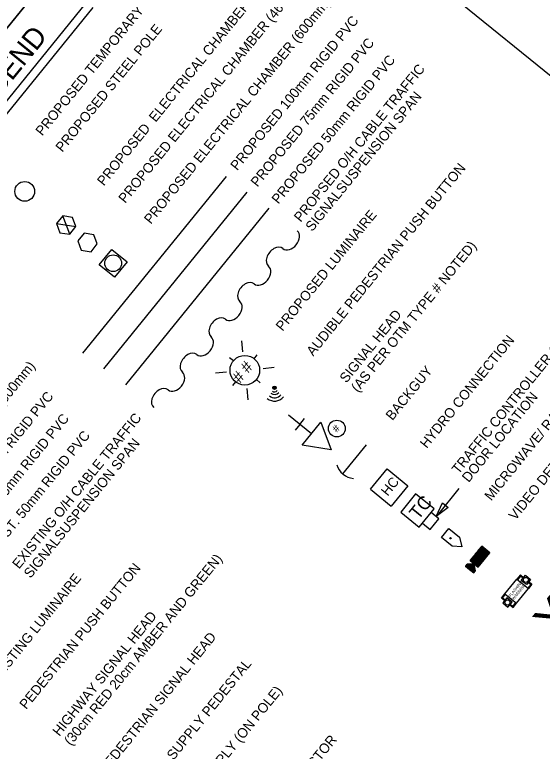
# Model space of a CAD drawing. Extents: x 592613 to 600223, y 4837996 to 4840103.
# Drawn here: x 592677.9 to 592701.09, y 4838962.54 to 4838994.9 of the extents above; entities that cross this region are included whole.
import ezdxf

# ---------------------------------------------------------------- set-up
doc = ezdxf.new("R2010")
doc.units = 0
for name, color, linetype in [('ENG_BORDER', 7, 'Continuous'), ('TCS_100mm-NEW', 7, 'Continuous'), ('TCS_50mm-NEW', 7, 'Continuous'), ('TCS_75mm-NEW', 7, 'Continuous'), ('TCS_BACKGUY', 7, 'Continuous'), ('TCS_CONTROLLER', 7, 'Continuous'), ('TCS_ELEC-CHAMBER-NEW', 7, 'Continuous'), ('TCS_HYDROSUPPLY', 7, 'Continuous'), ('TCS_LEGEND', 7, 'Continuous'), ('TCS_LUMINAIRE-NEW', 7, 'Continuous'), ('TCS_POLE-NEW', 7, 'Continuous'), ('TCS_PUSHBUTTON', 7, 'Continuous'), ('TCS_RADAR', 7, 'Continuous'), ('TCS_REMOVAL', 7, 'Continuous'), ('TCS_SIGN', 7, 'Continuous'), ('TCS_SIGNALHEAD', 7, 'Continuous'), ('TCS_SPAN-NEW', 7, 'Continuous'), ('TCS_VIDEO', 7, 'Continuous')]:
    doc.layers.add(name, color=color, linetype=linetype)

msp = doc.modelspace()

# ---------------------------------------------------------------- linework, layer by layer
at = {"layer": 'ENG_BORDER'}
msp.add_line((592790.401, 4838919.927), (592686.018, 4839004.737), dxfattribs=at)
msp.add_lwpolyline([(592783.858, 4839125.156), (592658.479, 4838970.843)], dxfattribs=at)
at = {"layer": 'TCS_100mm-NEW'}
msp.add_line((592680.903, 4838980.027), (592687.209, 4838987.788), dxfattribs=at)
at = {"layer": 'TCS_50mm-NEW'}
msp.add_line((592682.782, 4838978.641), (592689.088, 4838986.402), dxfattribs=at)
at = {"layer": 'TCS_75mm-NEW'}
msp.add_line((592681.814, 4838979.334), (592688.12, 4838987.095), dxfattribs=at)
at = {"layer": 'TCS_BACKGUY'}
msp.add_line((592692.323, 4838974.721), (592693.358, 4838975.995), dxfattribs=at)
msp.add_arc((592692.868, 4838975.372), 0.849, 196.7975, 265.0147, dxfattribs=at)
at = {"layer": 'TCS_CONTROLLER'}
for p, q in [((592697.428, 4838974.087), (592696.523, 4838972.973)), ((592695.524, 4838973.848), (592694.868, 4838973.04)), ((592696.332, 4838973.192), (592695.524, 4838973.848)), ((592694.868, 4838973.04), (592695.676, 4838972.384)), ((592695.676, 4838972.384), (592696.332, 4838973.192)), ((592696.54, 4838972.753), (592696.204, 4838973.026)), ((592696.158, 4838972.282), (592696.54, 4838972.753)), ((592695.821, 4838972.555), (592696.158, 4838972.282))]:
    msp.add_line(p, q, dxfattribs=at)
msp.add_lwpolyline([(592696.422, 4838972.849), (592696.701, 4838973.445), (592696.948, 4838973.244), (592696.948, 4838973.244)], close=True, dxfattribs=at)
at = {"layer": 'TCS_ELEC-CHAMBER-NEW'}
for p, q in [((592680.013, 4838986.06), (592679.74, 4838985.723)), ((592680.323, 4838985.249), (592680.013, 4838986.06)), ((592680.441, 4838985.991), (592680.013, 4838986.06)), ((592680.596, 4838985.586), (592680.441, 4838985.991)), ((592679.74, 4838985.723), (592680.596, 4838985.586)), ((592679.74, 4838985.723), (592679.894, 4838985.318)), ((592679.894, 4838985.318), (592680.323, 4838985.249)), ((592680.323, 4838985.249), (592680.596, 4838985.586)), ((592680.951, 4838985.297), (592680.678, 4838984.961)), ((592681.379, 4838985.229), (592680.951, 4838985.297)), ((592681.534, 4838984.824), (592681.379, 4838985.229)), ((592680.678, 4838984.961), (592680.832, 4838984.556)), ((592681.261, 4838984.487), (592681.534, 4838984.824)), ((592680.832, 4838984.556), (592681.261, 4838984.487)), ((592681.621, 4838983.915), (592682.168, 4838984.588)), ((592682.168, 4838984.588), (592682.842, 4838984.041)), ((592682.842, 4838984.041), (592682.295, 4838983.368)), ((592682.295, 4838983.368), (592681.621, 4838983.915))]:
    msp.add_line(p, q, dxfattribs=at)
msp.add_circle((592682.231, 4838983.978), 0.367, dxfattribs=at)
at = {"layer": 'TCS_HYDROSUPPLY'}
for p, q in [((592693.54, 4838974.045), (592694.269, 4838974.942)), ((592694.269, 4838974.942), (592695.175, 4838974.205)), ((592693.54, 4838974.045), (592694.447, 4838973.308)), ((592695.175, 4838974.205), (592694.447, 4838973.308))]:
    msp.add_line(p, q, dxfattribs=at)
at = {"layer": 'TCS_LEGEND'}
for p, q in [((592666.56, 4838977.581), (592681.077, 4838995.448)), ((592666.842, 4838977.353), (592681.359, 4838995.22))]:
    msp.add_line(p, q, dxfattribs=at)
msp.add_lwpolyline([(592661.217, 4838974.213), (592683.281, 4839001.368)], dxfattribs=at)
at = {"layer": 'TCS_LUMINAIRE-NEW'}
for p, q in [((592687.934, 4838980.085), (592687.884, 4838980.57)), ((592687.513, 4838979.686), (592687.344, 4838979.823)), ((592688.428, 4838979.781), (592688.565, 4838979.949)), ((592687.209, 4838979.192), (592686.724, 4838979.142)), ((592688.826, 4838979.36), (592689.312, 4838979.41)), ((592688.523, 4838978.866), (592688.691, 4838978.729)), ((592687.607, 4838978.771), (592687.471, 4838978.603)), ((592688.101, 4838978.468), (592688.152, 4838977.982))]:
    msp.add_line(p, q, dxfattribs=at)
msp.add_circle((592688.018, 4838979.276), 0.651, dxfattribs=at)
at = {"layer": 'TCS_POLE-NEW'}
msp.add_circle((592678.343, 4838987.137), 0.434, dxfattribs=at)
at = {"layer": 'TCS_PUSHBUTTON'}
for p, q in [((592689.251, 4838978.487), (592689.248, 4838978.512)), ((592689.26, 4838978.466), (592689.253, 4838978.534)), ((592689.269, 4838978.456), (592689.259, 4838978.546)), ((592689.277, 4838978.449), (592689.266, 4838978.554)), ((592689.284, 4838978.443), (592689.272, 4838978.561)), ((592689.292, 4838978.439), (592689.279, 4838978.566)), ((592689.3, 4838978.437), (592689.286, 4838978.571)), ((592689.307, 4838978.435), (592689.293, 4838978.574)), ((592689.314, 4838978.434), (592689.3, 4838978.577)), ((592689.322, 4838978.433), (592689.307, 4838978.579)), ((592689.329, 4838978.434), (592689.314, 4838978.58)), ((592689.336, 4838978.435), (592689.321, 4838978.58)), ((592689.343, 4838978.437), (592689.328, 4838978.58)), ((592689.35, 4838978.439), (592689.336, 4838978.579)), ((592689.357, 4838978.443), (592689.343, 4838978.577)), ((592689.364, 4838978.447), (592689.351, 4838978.574)), ((592689.371, 4838978.452), (592689.358, 4838978.57)), ((592689.377, 4838978.459), (592689.366, 4838978.565)), ((592689.384, 4838978.468), (592689.374, 4838978.557)), ((592689.39, 4838978.48), (592689.383, 4838978.547)), ((592689.394, 4838978.503), (592689.392, 4838978.525))]:
    msp.add_line(p, q, dxfattribs=at)
msp.add_circle((592689.321, 4838978.507), 0.0733, dxfattribs=at)
for centre, radius, start, end in [((592689.324, 4838978.429), 0.361, 230.9061, 320.9061), ((592689.318, 4838978.465), 0.253, 232.7914, 320.1073), ((592689.325, 4838978.475), 0.145, 230.9061, 320.9061), ((592689.324, 4838978.429), 0.506, 230.9061, 320.9061)]:
    msp.add_arc(centre, radius, start, end, dxfattribs=at)
at = {"layer": 'TCS_RADAR'}
msp.add_lwpolyline([(592696.656, 4838971.927), (592696.979, 4838972.326), (592697.448, 4838971.945), (592697.561, 4838971.514), (592697.124, 4838971.546)], close=True, dxfattribs=at)
for centre, radius in [((592697.054, 4838971.897), 0.0279), ((592697.056, 4838971.898), 0.0254), ((592697.059, 4838971.898), 0.0231), ((592697.061, 4838971.9), 0.021), ((592697.061, 4838971.9), 0.021), ((592697.062, 4838971.901), 0.0191)]:
    msp.add_circle(centre, radius, dxfattribs=at)
at = {"layer": 'TCS_SIGN'}
for p, q in [((592699.451, 4838969.458), (592699.969, 4838970.095)), ((592700.126, 4838970.288), (592699.969, 4838970.095)), ((592699.969, 4838970.095), (592700.478, 4838969.681)), ((592700.131, 4838970.237), (592699.997, 4838970.072)), ((592700.268, 4838970.172), (592700.126, 4838970.288)), ((592700.245, 4838970.144), (592700.131, 4838970.237)), ((592700.584, 4838969.869), (592700.45, 4838969.704)), ((592700.47, 4838969.962), (592700.584, 4838969.869)), ((592700.635, 4838969.874), (592700.478, 4838969.681)), ((592700.493, 4838969.99), (592700.635, 4838969.874)), ((592699.294, 4838969.264), (592699.451, 4838969.458)), ((592699.345, 4838969.27), (592699.479, 4838969.435)), ((592699.451, 4838969.458), (592699.96, 4838969.044)), ((592699.96, 4838969.044), (592700.478, 4838969.681)), ((592699.437, 4838969.149), (592699.294, 4838969.264)), ((592699.459, 4838969.177), (592699.345, 4838969.27)), ((592699.661, 4838968.966), (592699.803, 4838968.851)), ((592699.684, 4838968.994), (592699.798, 4838968.902)), ((592699.798, 4838968.902), (592699.932, 4838969.067)), ((592699.803, 4838968.851), (592699.96, 4838969.044))]:
    msp.add_line(p, q, dxfattribs=at)
for points in [[(592700.572, 4838970.088), (592700.39, 4838969.864), (592700.166, 4838970.046), (592700.348, 4838970.271)], [(592699.581, 4838968.868), (592699.764, 4838969.093), (592699.539, 4838969.275), (592699.357, 4838969.051)]]:
    msp.add_lwpolyline(points, close=True, dxfattribs=at)
for centre in [(592700.369, 4838970.067), (592699.56, 4838969.072)]:
    msp.add_circle(centre, 0.111, dxfattribs=at)
at = {"layer": 'TCS_SIGNALHEAD'}
for p, q in [((592690.942, 4838976.487), (592689.932, 4838977.307)), ((592690.437, 4838976.897), (592690.232, 4838976.645)), ((592690.437, 4838976.897), (592690.642, 4838977.15)), ((592690.532, 4838975.982), (592691.352, 4838976.992)), ((592691.352, 4838976.992), (592691.817, 4838975.776)), ((592691.817, 4838975.776), (592690.532, 4838975.982))]:
    msp.add_line(p, q, dxfattribs=at)
msp.add_circle((592692.06, 4838976.715), 0.368, dxfattribs=at)
at = {"layer": 'TCS_SPAN-NEW'}
for centre, start_param, end_param in [((592690.006, 4838985.011), 3.141593, 6.283185), ((592689.375, 4838984.235), 0, 3.141593), ((592688.744, 4838983.459), 3.141593, 6.283185), ((592688.113, 4838982.684), 6.283185, 9.424778), ((592687.483, 4838981.908), 3.141593, 6.283185), ((592686.852, 4838981.132), 6.283185, 9.424778), ((592686.221, 4838980.356), 3.141593, 6.283185), ((592685.59, 4838979.58), 0, 3.141593), ((592684.959, 4838978.804), 3.141593, 6.283185), ((592684.328, 4838978.028), 0, 3.141593)]:
    msp.add_ellipse(centre, major_axis=(0.315, 0.388), ratio=0.7, start_param=start_param, end_param=end_param, dxfattribs=at)
at = {"layer": 'TCS_VIDEO'}
for p, q in [((592698.359, 4838970.72), (592698.29, 4838971.381)), ((592698.372, 4838970.736), (592698.303, 4838971.397)), ((592698.384, 4838970.752), (592698.316, 4838971.413)), ((592698.397, 4838970.768), (592698.329, 4838971.428)), ((592698.41, 4838970.784), (592698.342, 4838971.444)), ((592698.423, 4838970.8), (592698.355, 4838971.46)), ((592698.436, 4838970.816), (592698.368, 4838971.476)), ((592698.449, 4838970.831), (592698.381, 4838971.492)), ((592698.462, 4838970.847), (592698.393, 4838971.508)), ((592698.475, 4838970.863), (592698.406, 4838971.524)), ((592698.488, 4838970.879), (592698.419, 4838971.539)), ((592698.5, 4838970.895), (592698.433, 4838971.543)), ((592698.513, 4838970.911), (592698.449, 4838971.53)), ((592698.526, 4838970.927), (592698.465, 4838971.517)), ((592698.539, 4838970.942), (592698.481, 4838971.504)), ((592698.552, 4838970.958), (592698.497, 4838971.491)), ((592698.565, 4838970.974), (592698.513, 4838971.478)), ((592698.578, 4838970.99), (592698.529, 4838971.465)), ((592698.591, 4838971.006), (592698.545, 4838971.453)), ((592698.604, 4838971.022), (592698.56, 4838971.44)), ((592698.617, 4838971.038), (592698.576, 4838971.427)), ((592698.629, 4838971.054), (592698.592, 4838971.414)), ((592698.642, 4838971.069), (592698.608, 4838971.401)), ((592698.655, 4838971.085), (592698.624, 4838971.388)), ((592698.06, 4838970.799), (592698.032, 4838971.063)), ((592698.076, 4838970.786), (592698.045, 4838971.079)), ((592698.092, 4838970.773), (592698.058, 4838971.095)), ((592698.107, 4838970.76), (592698.071, 4838971.111)), ((592698.123, 4838970.747), (592698.084, 4838971.127)), ((592698.139, 4838970.734), (592698.097, 4838971.143)), ((592698.155, 4838970.721), (592698.11, 4838971.159)), ((592698.171, 4838970.708), (592698.123, 4838971.174)), ((592698.187, 4838970.695), (592698.136, 4838971.19)), ((592698.203, 4838970.682), (592698.148, 4838971.206)), ((592698.219, 4838970.67), (592698.161, 4838971.222)), ((592698.234, 4838970.657), (592698.174, 4838971.238)), ((592698.25, 4838970.644), (592698.187, 4838971.254)), ((592698.266, 4838970.631), (592698.2, 4838971.27)), ((592698.281, 4838970.625), (592698.213, 4838971.286)), ((592698.294, 4838970.641), (592698.226, 4838971.301)), ((592698.307, 4838970.657), (592698.239, 4838971.317)), ((592698.32, 4838970.673), (592698.252, 4838971.333)), ((592698.333, 4838970.689), (592698.265, 4838971.349)), ((592698.346, 4838970.704), (592698.277, 4838971.365)), ((592698.668, 4838971.101), (592698.64, 4838971.375)), ((592698.681, 4838971.117), (592698.656, 4838971.362)), ((592698.694, 4838971.133), (592698.671, 4838971.349)), ((592698.707, 4838971.149), (592698.687, 4838971.337)), ((592698.72, 4838971.165), (592698.703, 4838971.324)), ((592698.733, 4838971.18), (592698.719, 4838971.311)), ((592698.745, 4838971.196), (592698.735, 4838971.298)), ((592698.758, 4838971.212), (592698.751, 4838971.285)), ((592698.771, 4838971.228), (592698.767, 4838971.272)), ((592698.784, 4838971.244), (592698.783, 4838971.259)), ((592697.787, 4838970.761), (592697.713, 4838970.67)), ((592697.781, 4838970.614), (592697.768, 4838970.738)), ((592697.797, 4838970.601), (592697.781, 4838970.754)), ((592698.096, 4838970.769), (592697.787, 4838970.761)), ((592697.813, 4838970.588), (592697.795, 4838970.761)), ((592697.829, 4838970.575), (592697.81, 4838970.762)), ((592697.845, 4838970.563), (592697.824, 4838970.762)), ((592697.861, 4838970.55), (592697.839, 4838970.762)), ((592697.877, 4838970.537), (592697.853, 4838970.763)), ((592697.892, 4838970.524), (592697.868, 4838970.763)), ((592697.908, 4838970.511), (592697.882, 4838970.764)), ((592697.924, 4838970.498), (592697.897, 4838970.764)), ((592697.94, 4838970.485), (592697.911, 4838970.764)), ((592697.917, 4838970.915), (592697.916, 4838970.921)), ((592697.956, 4838970.472), (592697.926, 4838970.765)), ((592697.933, 4838970.902), (592697.929, 4838970.936)), ((592697.972, 4838970.459), (592697.94, 4838970.765)), ((592697.949, 4838970.889), (592697.942, 4838970.952)), ((592697.965, 4838970.876), (592697.955, 4838970.968)), ((592697.988, 4838970.446), (592697.955, 4838970.765)), ((592697.98, 4838970.863), (592697.968, 4838970.984)), ((592698.003, 4838970.434), (592697.969, 4838970.766)), ((592697.996, 4838970.85), (592697.981, 4838971)), ((592698.019, 4838970.421), (592697.984, 4838970.766)), ((592698.012, 4838970.837), (592697.994, 4838971.016)), ((592698.035, 4838970.408), (592697.998, 4838970.767)), ((592698.028, 4838970.824), (592698.007, 4838971.032)), ((592698.051, 4838970.395), (592698.013, 4838970.767)), ((592698.044, 4838970.811), (592698.02, 4838971.048)), ((592698.067, 4838970.382), (592698.027, 4838970.767)), ((592698.082, 4838970.38), (592698.042, 4838970.768)), ((592698.095, 4838970.395), (592698.056, 4838970.768)), ((592698.108, 4838970.411), (592698.071, 4838970.769)), ((592698.12, 4838970.427), (592698.085, 4838970.769)), ((592698.151, 4838970.465), (592698.096, 4838970.769)), ((592697.713, 4838970.67), (592697.895, 4838970.522)), ((592697.718, 4838970.666), (592697.717, 4838970.675)), ((592697.734, 4838970.653), (592697.73, 4838970.691)), ((592697.75, 4838970.64), (592697.743, 4838970.707)), ((592697.765, 4838970.627), (592697.756, 4838970.723)), ((592697.895, 4838970.522), (592698.077, 4838970.374)), ((592698.077, 4838970.374), (592698.151, 4838970.465)), ((592698.133, 4838970.443), (592698.104, 4838970.722)), ((592698.146, 4838970.459), (592698.138, 4838970.535))]:
    msp.add_line(p, q, dxfattribs=at)
msp.add_lwpolyline([(592698.278, 4838970.621), (592698.791, 4838971.252), (592698.427, 4838971.548), (592697.914, 4838970.917), (592698.096, 4838970.769), (592698.278, 4838970.621)], dxfattribs=at)

# ---------------------------------------------------------------- texts
at = {"layer": 'TCS_CONTROLLER'}
msp.add_text('TC', height=0.5783, rotation=50.9061, dxfattribs=at).set_placement((592695.64, 4838972.673))
at = {"layer": 'TCS_HYDROSUPPLY'}
msp.add_text('HC', height=0.4337, rotation=50.9061, dxfattribs=at).set_placement((592694.298, 4838973.716))
at = {"layer": 'TCS_LEGEND'}
for s, height, p in [('PROPOSED TEMPORARY WOODEN POLE', 0.43374, (592679.116, 4838989.545)), ('PROPOSED  ELECTRICAL CHAMBER (300mm)', 0.43374, (592681.822, 4838987.346)), ('PROPOSED ELECTRICAL CHAMBER (460mm)', 0.43374, (592682.76, 4838986.584)), ('PROPOSED ELECTRICAL CHAMBER (600mm)', 0.43374, (592683.886, 4838985.67)), ('PROPOSED 100mm RIGID PVC', 0.43374, (592687.68, 4838988.024)), ('PROPOSED STEEL POLE', 0.43374, (592679.997, 4838988.829)), ('TRAFFIC SYMBOLS LEGEND', 0.90363, (592668.925, 4838981.067)), ('PROPOSED 75mm RIGID PVC', 0.43374, (592688.571, 4838987.3)), ('PROPOSED 50mm RIGID PVC', 0.43374, (592689.493, 4838986.55)), ('PROPSED O/H CABLE TRAFFIC', 0.43374, (592690.473, 4838985.754)), ('SIGNALSUSPENSION SPAN', 0.43374, (592690.978, 4838985.344)), ('AUDIBLE PEDESTRIAN PUSH BUTTON', 0.43374, (592691.022, 4838979.872)), ('PROPOSED LUMINAIRE', 0.43374, (592689.674, 4838980.967)), ('(AS PER OTM TYPE # NOTED)', 0.43374, (592692.983, 4838978.278)), ('TRAFFIC CONTROLLER CABINET', 0.43374, (592697.41, 4838974.681)), ('SIGNAL HEAD ', 0.43374, (592692.479, 4838978.688)), ('HYDRO CONNECTION', 0.43374, (592696.012, 4838975.817)), ('MICROWAVE/ RADAR DETECTOR', 0.43374, (592698.845, 4838973.515)), ('EXISTING ELECTRICAL CHAMBER (600mm)', 0.43374, (592671.273, 4838970.147)), ('BACKGUY', 0.4337, (592694.504, 4838977.042)), ('EXIST. 100mm RIGID PVC', 0.43374, (592675.183, 4838972.643)), ('DOOR LOCATION', 0.43374, (592697.856, 4838974.319)), ('EXIST. 75mm RIGID PVC', 0.43374, (592676.074, 4838971.919)), ('EXISTING O/H CABLE TRAFFIC', 0.43374, (592678.094, 4838970.519)), ('EXIST. 50mm RIGID PVC', 0.43374, (592676.997, 4838971.17)), ('VIDEO DETECTOR', 0.43374, (592699.906, 4838972.653)), ('SIGNALSUSPENSION SPAN', 0.43374, (592678.599, 4838970.109)), ('(30cm RED 20cm AMBER AND GREEN)', 0.43374, (592680.371, 4838962.755)), ('PEDESTRIAN PUSH BUTTON', 0.43374, (592678.409, 4838964.349)), ('EXISTING LUMINAIRE', 0.43374, (592677.055, 4838965.449)), ('HIGHWAY SIGNAL HEAD ', 0.43374, (592679.866, 4838963.165)), ('PEDESTRIAN SIGNAL HEAD', 0.43374, (592681.892, 4838961.519)), ('POWER SUPPLY PEDESTAL', 0.43374, (592683.4, 4838960.294)), ('POWER SUPPLY (ON POLE)', 0.43374, (592684.798, 4838959.158)), ('VEHICLE LOOP DETECTOR', 0.43374, (592687.294, 4838957.13))]:
    msp.add_text(s, height=height, rotation=50.9061, dxfattribs=at).set_placement(p)
at = {"layer": 'TCS_LUMINAIRE-NEW'}
msp.add_text('# #', height=0.506, rotation=50.9061, dxfattribs=at).set_placement((592687.813, 4838978.682))
at = {"layer": 'TCS_REMOVAL'}
msp.add_text('X', height=1.631, rotation=50.9061, dxfattribs=at).set_placement((592701.842, 4838967.34))
at = {"layer": 'TCS_SIGN'}
for s, p in [('FLASHING', (592699.692, 4838969.293)), ('WARNING', (592699.84, 4838969.173))]:
    msp.add_text(s, height=0.1265, rotation=50.9061, dxfattribs=at).set_placement(p)
at = {"layer": 'TCS_SIGNALHEAD'}
msp.add_text('#', height=0.325, rotation=50.9061, dxfattribs=at).set_placement((592692.073, 4838976.523))

doc.saveas('drawing.dxf')
